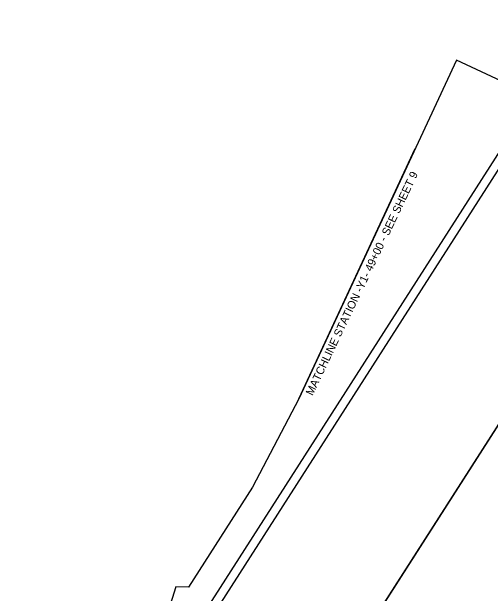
# Model space of a CAD drawing. Extents: x 2346049 to 2349719, y 842061 to 846435.
# Drawn here: x 2347924 to 2348821, y 843342 to 844432 of the extents above; entities that cross this region are included whole.
import ezdxf

# ---------------------------------------------------------------- set-up
doc = ezdxf.new("R2010")
doc.units = 0
for name, color, linetype in [('Matchline', 7, 'Continuous'), ('Matchline Text', 7, 'Continuous'), ('Scratch_Level_0', 7, 'Continuous'), ('Sheet Cutting Line CELL', 7, 'Continuous'), ('Sheet Detail CELL', 7, 'Continuous'), ('Sheet Plot Border Inside CELL', 7, 'Continuous'), ('Sheet Plot Border Outside CELL', 7, 'Continuous')]:
    doc.layers.add(name, color=color, linetype=linetype)

msp = doc.modelspace()

# ---------------------------------------------------------------- linework, layer by layer
at = {"layer": 'Matchline'}
msp.add_line((2348462.4, 843706.5), (2348680.6, 844175.2), dxfattribs=at)
at = {"layer": 'Scratch_Level_0'}
for points in [[(2349350.4, 845074.8), (2348851.8, 844297.2), (2348757.8, 844341), (2348462.4, 843706.5), (2348375.3, 843541.3), (2348255.5, 843353.8), (2348231.9, 843354.7), (2348207.8, 843279), (2348000.9, 842955.2), (2347829, 843060.7), (2347638.3, 842833.8), (2347080.7, 843191.4), (2347008.6, 843443.9), (2347324.8, 843936.9), (2346937.8, 844263.6), (2347160.2, 844610.4)], [(2349350.4, 845074.8), (2348851.8, 844297.2), (2348757.8, 844341), (2348462.4, 843706.5), (2348375.3, 843541.3), (2348255.5, 843353.8), (2348231.9, 843354.7), (2348207.8, 843279), (2348000.9, 842955.2), (2347829, 843060.7), (2347638.3, 842833.8), (2347080.7, 843191.4), (2347008.6, 843443.9), (2347324.8, 843936.9), (2346961.1, 844244), (2347005, 844312.5), (2347188.2, 844598.2)], [(2349350.4, 845074.8), (2348851.8, 844297.2), (2348757.8, 844341), (2348462.4, 843706.5), (2348375.3, 843541.3), (2348255.5, 843353.8), (2348231.9, 843354.7), (2348207.8, 843279), (2348000.9, 842955.2), (2347829, 843060.7), (2347638.3, 842833.8), (2347080.7, 843191.4), (2347008.6, 843443.9), (2347324.8, 843936.9), (2346961.1, 844244), (2347005, 844312.5), (2347188.2, 844598.2)]]:
    msp.add_lwpolyline(points, dxfattribs=at)
at = {"layer": 'Sheet Cutting Line CELL'}
msp.add_line((2347900.5, 842198.8), (2349718.7, 845033.9), dxfattribs=at)
msp.add_line((2347900.5, 842198.8), (2349718.7, 845033.9), dxfattribs=at)
at = {"layer": 'Sheet Detail CELL'}
msp.add_lwpolyline([(2346465.3, 843526.7), (2348084.7, 846052), (2349473.7, 845161.3), (2347854.2, 842636)], close=True, dxfattribs=at)
at = {"layer": 'Sheet Plot Border Inside CELL'}
msp.add_lwpolyline([(2348083.9, 846082.3), (2346302.5, 843304.4), (2347720, 842395.3), (2349501.5, 845173.2)], close=True, dxfattribs=at)
at = {"layer": 'Sheet Plot Border Outside CELL'}
msp.add_lwpolyline([(2347866.8, 846221.5), (2346048.7, 843386.4), (2347900.5, 842198.8), (2349718.7, 845033.9)], close=True, dxfattribs=at)

# ---------------------------------------------------------------- texts
at = {"layer": 'Matchline Text'}
msp.add_text('MATCHLINE STATION -Y1- 49+00 - SEE SHEET 9', height=15, rotation=64.5562, dxfattribs=at).set_placement((2348488.1, 843711.5))

doc.saveas('drawing.dxf')
